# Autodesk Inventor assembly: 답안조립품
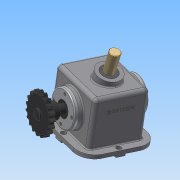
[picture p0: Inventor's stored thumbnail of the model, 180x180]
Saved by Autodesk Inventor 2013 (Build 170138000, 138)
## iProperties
Created: 2014-11
Part Number: 답안조립품
Document SubType Name: Assembly
Designer: Administrator
Author: Administrator
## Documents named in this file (13)
- C:\Users\Administrator\Desktop\441123V1028\441123V1028\답안조립품.iam
- C:\Users\Administrator\Desktop\441123V1028\본체.ipt
- C:\Users\Administrator\Desktop\441123V1028\441123V1028\5-체인 스프로킷.ipt
- C:\Users\Administrator\Desktop\441123V1028\441123V1028\M4x0.5.ipt
- C:\Users\Administrator\Desktop\441123V1028\441123V1028\뒤커버.ipt
- C:\Users\Administrator\Desktop\441123V1028\441123V1028\멈춤나사 M5x0.5.ipt
- C:\Users\Administrator\Desktop\441123V1028\441123V1028\베어링 6205.ipt
- C:\Users\Administrator\Desktop\441123V1028\441123V1028\부시.ipt
- C:\Users\Administrator\Desktop\441123V1028\441123V1028\슬라이드.ipt
- C:\Users\Administrator\Desktop\441123V1028\441123V1028\앞커버.ipt
- C:\Users\Administrator\Desktop\441123V1028\441123V1028\오일실.ipt
- C:\Users\Administrator\Desktop\441123V1028\441123V1028\키 8x8.ipt
- C:\Users\Administrator\Desktop\441123V1028\441123V1028\편심축.ipt
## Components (10 placed, 2 different names)
1. 5-체인 스프로킷:1 — Mate:3, Flush:1, Mate:17
2. M4x0.5:2
3. M4x0.5:1 — Insert:7
4. M4x0.5:3 — Insert:6
5. M4x0.5:4
6. M4x0.5:5
7. M4x0.5:6
8. M4x0.5:7
9. M4x0.5:8
10. M4x0.5:9
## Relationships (5: Mate 2, Insert 2, Flush 1)
- Mate:3: 5-체인 스프로킷:1
- Flush:1: 5-체인 스프로킷:1
- Mate:17: 5-체인 스프로킷:1
- Insert:6: M4x0.5:3
- Insert:7: M4x0.5:1
